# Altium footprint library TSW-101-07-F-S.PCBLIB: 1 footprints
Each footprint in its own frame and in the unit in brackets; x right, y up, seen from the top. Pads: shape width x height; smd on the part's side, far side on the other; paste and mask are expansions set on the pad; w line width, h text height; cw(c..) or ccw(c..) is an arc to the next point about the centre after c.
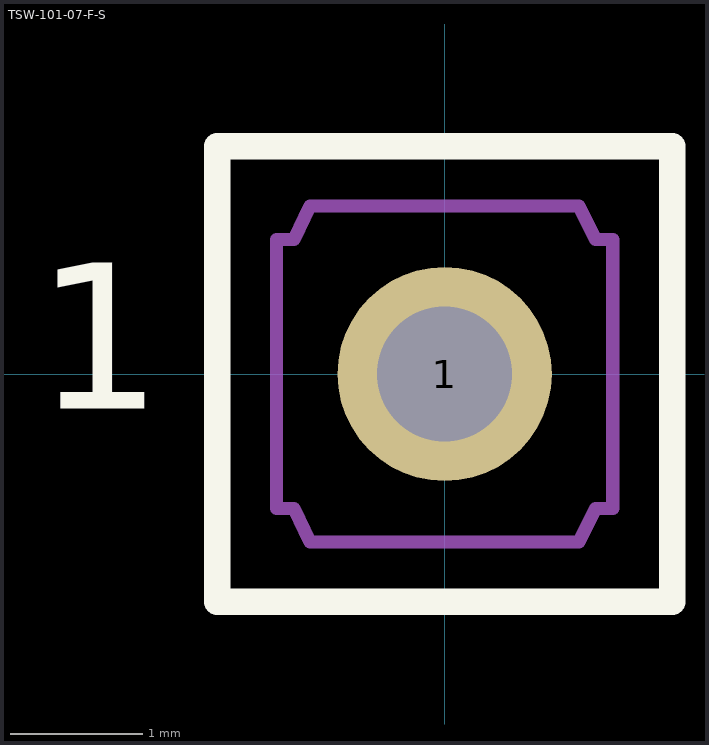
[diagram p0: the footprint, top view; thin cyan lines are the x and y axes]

## TSW-101-07-F-S [mm]
pads (1):
  round 1.62 hole 1.02: 1(0,0)
Top Overlay:
  lines w0.2: -1.72,-1.72 -1.72,1.72 1.72,1.72 1.72,-1.72 -1.72,-1.72
  text "1" at -3.09,-0.635 h1.97
Top Solder:
  circle w0: c0,0 r0.861
Bottom Solder:
  circle w0: c0,0 r0.861
Mechanical 16:
  lines w0.1: -1.27,-1.016 -1.14,-1.016 -1.016,-1.27 1.016,-1.27 1.14,-1.016 1.27,-1.016 1.27,1.016 1.14,1.016 1.016,1.27 -1.016,1.27 -1.14,1.016 -1.27,1.016 -1.27,-1.016 ; -0.318,-0.318 -0.318,0.318 0.318,0.318 0.318,-0.318 -0.318,-0.318
  text "1" at -3.09,-0.635 h1.97
Mechanical 42:
  lines w0.1: -1.72,-1.72 -1.72,1.72 1.72,1.72 1.72,-1.72 -1.72,-1.72
3D body "TSW-101-07-F-S.stp": height 8.38, standoff -2.54, extent -1.27,-1.27 1.27,1.27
